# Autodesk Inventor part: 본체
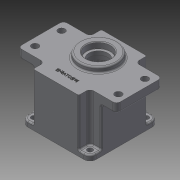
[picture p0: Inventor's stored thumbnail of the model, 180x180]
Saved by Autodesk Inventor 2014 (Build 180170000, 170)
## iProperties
Created: 2015-07
Part Number: 본체
Material: Generic
Document SubType Name: Modeling
Designer: Administrator
Density: 1 g/cm^3
Appearance: Default
Author: Administrator
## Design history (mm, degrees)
sketch "스케치1"
  geometry: L1 (45, -45)-(-45, -45); L2 (-45, -45)-(-45, 45); L3 (-45, 45)-(45, 45); L4 (45, 45)-(45, -45); L5 (45, -45)-(-45, 45); L6 (-45, -45)-(45, 45); 1 further point
  constraints: 12 end point, 2 midpoint, 2 parallel, 1 horizontal, 1 perpendicular
  dimensions: "d0" = 90 distance of L2.end L3.end; "d1" = 90 distance of L1.end L2.end
extrude "돌출1" new body sketch "스케치1" distance "d2" = 58; taper "d3" = 0 deg
sketch "스케치2"
  geometry: L1 (45, 45)-(-45, 45) reference; L2 (65, -30)-(-65, -30); L3 (-65, -30)-(-65, 30); L4 (-65, 30)-(65, 30); L5 (65, 30)-(65, -30); L6 (65, -30)-(-65, 30); L7 (-65, -30)-(65, 30); L8 (30, -45)-(-30, -45); L9 (-30, -45)-(-30, 45); L10 (-30, 45)-(30, 45); L11 (30, 45)-(30, -45); L12 (30, -45)-(-30, 45); L13 (-30, -45)-(30, 45); 1 further point
  constraints: 24 end point, 4 midpoint, 4 parallel, 2 horizontal, 2 perpendicular, 1 point on line
  dimensions: "d4" = 60 distance between parallel lines of L9 L11; "d5" = 60 distance between parallel lines of L4 L2; "d6" = 130 distance between parallel lines of L3 L5
extrude "돌출2" join sketch "스케치2" distance "d7" = 12; taper "d8" = 0 deg
sketch "스케치3"
  geometry: L1 (30, -30)-(30, -45) reference; L2 (30, -45)-(45, -45) reference; L3 (45, -45)-(45, -30) reference; L4 (45, -30)-(30, -30) reference; L5 (-30, -30)-(-45, -30) reference; L6 (-45, -30)-(-45, -45) reference; L7 (-45, -45)-(-30, -45) reference; L8 (-30, -45)-(-30, -30) reference; L9 (-45, 30)-(-30, 30) reference; L10 (-30, 30)-(-30, 45) reference; L11 (-30, 45)-(-45, 45) reference; L12 (-45, 45)-(-45, 30) reference; L13 (30, 45)-(30, 30) reference; L14 (30, 30)-(45, 30) reference; L15 (45, 30)-(45, 45) reference; L16 (45, 45)-(30, 45) reference; 1 further point
extrude "돌출3" cut sketch "스케치3" distance "d9" = 51; taper "d10" = 0 deg
sketch "스케치4"
  geometry: C1 r 40 at (0, 0); 1 further point
  constraints: 1 centre point, 1 coincident
  dimensions: "d12" = 80 diameter of C1
extrude "돌출4" cut sketch "스케치4" distance "d13" = 9; taper "d14" = 0 deg
sketch "스케치5"
  geometry: C1 r 40 at (0, 0) reference; C2 r 39 at (0, 0)
  constraints: 1 centre point, 1 coincident
  dimensions: "d15" = 78 diameter of C2
extrude "돌출5" cut sketch "스케치5" distance "d16" = 52; taper "d17" = 0 deg
sketch "스케치6"
  geometry: C1 r 39 at (0, 0) reference; C2 r 20.5 at (0, 11); C3 r 14 at (0, -20)
  constraints: 2 centre point, 2 vertical alignment
  dimensions: "d18" = 20.5 radius of C2; "d19" = 14 radius of C3; "d20" = 11 distance of C1.centre C2.centre; "d21" = 20 distance of C3.centre C1.centre
extrude "돌출6" join sketch "스케치6" distance "d22" = 7; taper "d23" = 0 deg
sketch "스케치7"
  geometry: C1 r 17.5 at (0, 11); A1 r 20.5 centre (0, 11) between (7.402, -8.117) and (-7.402, -8.117) reference; 1 further point
  constraints: 1 centre point, 1 coincident
  dimensions: "d25" = 35 diameter of C1
extrude "돌출7" cut sketch "스케치7" distance "d26" = 10; taper "d27" = 0 deg
sketch "스케치8"
  geometry: C1 r 17.5 at (0, 0) reference; C2 r 12.5 at (0, 0); 1 further point
  constraints: 1 centre point, 1 coincident
  dimensions: "d28" = 25 diameter of C2
extrude "돌출8" cut sketch "스케치8" distance "d29" = 5; taper "d30" = 0 deg
sketch "스케치9"
  geometry: C1 r 11 at (0, -20); A1 r 14 centre (0, -20) between (-7.402, -8.117) and (7.402, -8.117) reference; 1 further point
  constraints: 1 centre point, 1 coincident
  dimensions: "d31" = 22 diameter of C1
extrude "돌출9" cut sketch "스케치9" distance "d32" = 7; taper "d33" = 0 deg
sketch "스케치10"
  geometry: C1 r 11 at (0, 0) reference; C2 r 9.5 at (0, 0); 1 further point
  constraints: 1 centre point, 1 coincident
  dimensions: "d34" = 19 diameter of C2
extrude "돌출10" cut sketch "스케치10" distance "d35" = 1; taper "d36" = 0 deg
sketch "스케치11"
  geometry: C1 r 12.5 at (0, 11) reference; C2 r 25 at (0, 11); 1 further point
  constraints: 1 centre point, 1 coincident
  dimensions: "d37" = 50 diameter of C2
extrude "돌출11" join sketch "스케치11" distance "d38" = 7; taper "d39" = 0 deg
sketch "스케치12"
  geometry: C1 r 25 at (0, 0) reference; C2 r 16 at (0, 0); 1 further point
  constraints: 1 centre point, 1 coincident
  dimensions: "d40" = 32 diameter of C2
extrude "돌출12" cut sketch "스케치12" distance "d41" = 8; taper "d42" = 0 deg
sketch "스케치13"
  geometry: L1 (-24.749, -24.749)-(0, 0); L2 (0, 0)-(-35, 0); C1 r 40 at (0, 0) reference; A1 r 39 centre (0, 0) between (-21.134, -32.777) and (-32.777, -21.134) reference; A2 r 35 centre (0, 0) between (-24.749, -24.749) and (-35, 0); A3 r 4 centre (-24.749, -24.749) between (-21.809, -27.462) and (-27.462, -21.809); A4 r 3.5 centre (-29.836, -19.238) between (-32.777, -21.134) and (-27.412, -21.762); A5 r 3.5 centre (-19.238, -29.836) between (-21.762, -27.412) and (-21.134, -32.777)
  constraints: 14 point on circle, 4 centre point, 4 end point, 4 tangent, 1 coincident, 1 horizontal
  dimensions: "d43" = 35 radius of A2; "d44" = 4 radius of A3; "d45" = 45 deg angle of L1 L2; "d46" = 3.5 radius of A4; "d47" = 3.5 radius of A5
extrude "돌출13" join sketch "스케치13" stored distance "d48" = 8; taper "d49" = 0 deg
sketch "스케치14"
  geometry: A1 r 4 centre (-24.749, -24.749) between (-21.809, -27.462) and (-27.462, -21.809) reference; 1 further point
  constraints: 1 coincident
hole "구멍1" sketch "스케치14" at (-24.749, -24.749) diameter "d50" = 3.459; stored, may be unused: countersink angle "d54" = 90 deg, drill point angle "d56" = 118 deg; dims "d51" = 12, "d52" = 4, "d53" = 2, "d55" = 15
fillet "모깎기1" dims "d60" = 8
sketch "스케치15"
  geometry: L1 (-45, -37)-(-45, 37) reference; L2 (-37, 45)-(37, 45) reference; L3 (45, 37)-(45, -37) reference; L4 (37, -45)-(-37, -45) reference; C1 r 40 at (0, 0) reference; C2 r 3.5 at (-37, 37); C3 r 3.5 at (37, 37); C4 r 3.5 at (37, -37); C5 r 3.5 at (-37, -37); A1 r 8 centre (-37, -37) between (-45, -37) and (-37, -45) reference; A2 r 8 centre (-37, 37) between (-37, 45) and (-45, 37) reference; A3 r 8 centre (37, 37) between (45, 37) and (37, 45) reference; A4 r 8 centre (37, -37) between (37, -45) and (45, -37) reference; 1 further point
  constraints: 4 centre point, 4 coincident
  dimensions: "d61" = 7 diameter of C2; "d62" = 7 diameter of C3; "d63" = 7 diameter of C4; "d64" = 7 diameter of C5
extrude "돌출14" cut sketch "스케치15" stored distance "d65" = 8; taper "d66" = 0 deg
fillet "모깎기2" dims "d67" = 5
sketch "스케치16"
  geometry: C1 r 4.5 at (-55, 17.5); C2 r 4.5 at (55, 17.5); C3 r 4.5 at (55, -17.5); C4 r 4.5 at (-55, -17.5); 1 further point
  constraints: 4 centre point, 2 horizontal alignment, 2 vertical alignment
  dimensions: "d68" = 9 diameter of C1; "d69" = 9 diameter of C2; "d70" = 9 diameter of C3; "d71" = 9 diameter of C4; "d72" = 110 distance of C2.centre C1.centre; "d73" = 35 distance of C2.centre C3.centre; "d74" = 55 horizontal distance of point (0, 0) C2.centre; "d75" = 17.5 vertical distance of point (0, 0) C3.centre
extrude "돌출15" cut sketch "스케치16" stored distance "d76" = 8; taper "d77" = 0 deg
sketch "스케치17"
  geometry: L1 (-30, -45)-(30, -45) reference; 2 further points
  constraints: 1 vertical alignment, 1 other
  dimensions: "d78" = 15 distance from line of L1 point (0, -30)
feature "엠보싱1" sketch "스케치17" dims "d6" = 130, "d79" = 0.5, "d80" = 0
fillet "모깎기3" dims "d81" = 5
fillet "모깎기4" dims "d82" = 3
fillet "모깎기5" dims "d83" = 2
fillet "모깎기6" dims "d84" = 2
fillet "모깎기7" dims "d85" = 2
fillet "모깎기8" dims "d86" = 2
fillet "모깎기9" dims "d87" = 2
fillet "모깎기10" dims "d88" = 2
fillet "모깎기11" dims "d89" = 2
fillet "모깎기12" dims "d90" = 0.3
chamfer "모따기1" distance "d91" = 1; stored, may be unused: second distance "d92" = 2, angle "d93" = 45 deg
node "솔리드1"
pattern_circular "원형 패턴1" dims angle "d58" = 360 deg
node "투영된 루프1"
node "투영된 루프2"
node "투영된 루프3"
node "투영된 루프4"
node "투영된 루프5"
